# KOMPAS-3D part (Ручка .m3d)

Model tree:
1. Эскиз:8
2. Операция выдавливания:4
     Расстояние 1 = 16; Расстояние 2 = 16
3. Скругление:10
     Радиус = 12
4. Скругление:11
     Радиус = 12
5. Эскиз:9
6. Вырезать элемент выдавливания:2
     Расстояние 1 = 20
7. Скругление:12
     Радиус = 12
